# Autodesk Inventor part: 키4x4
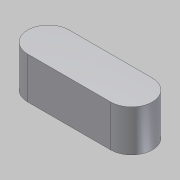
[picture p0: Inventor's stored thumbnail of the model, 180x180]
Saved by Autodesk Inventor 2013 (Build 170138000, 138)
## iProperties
Created: 2013-08
Part Number: 키4x4
Document SubType Name: Modeling
Designer: 한국산업디자인학원
Density: 1 g/cm^3
Material: 일반
Author: 한국산업디자인학원
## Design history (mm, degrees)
sketch "스케치1"
  geometry: L1 (-10, 2)-(-2, 2) reference; L2 (-2, -2)-(-10, -2) reference; A1 r 2 centre (-2, 0) between (-2, -2) and (-2, 2) reference; A2 r 2 centre (-10, 0) between (-10, 2) and (-10, -2) reference; 1 further point
extrude "돌출1" new body sketch "스케치1" distance "d0" = 4; taper "d1" = 0 deg
node "솔리드1"
node "참조1"
